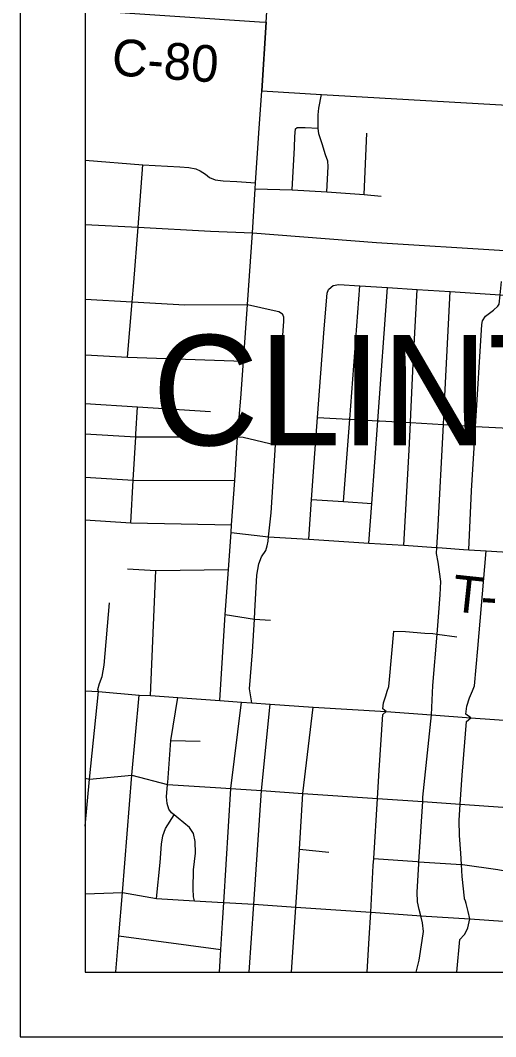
# Model space of a CAD drawing. Extents: x 0 to 34, y 0 to 22.
# Drawn here: x 2 to 2.735, y 14 to 15.572 of the extents above; entities that cross this region are included whole.
import ezdxf

# ---------------------------------------------------------------- set-up
doc = ezdxf.new("R2010")
doc.units = 0
for name, color, linetype in [('GM_X_City_Street', 7, 'Continuous'), ('GM_X_Corporation', 7, 'Continuous'), ('GM_X_County_Road', 7, 'Continuous'), ('GM_X_County_Road_Text', 7, 'Continuous'), ('GM_X_Township_Road', 7, 'Continuous'), ('GM_X_Township_Road_Text', 7, 'Continuous'), ('GM_X_Township_Text', 7, 'Continuous'), ('SH_Data', 7, 'Continuous')]:
    doc.layers.add(name, color=color, linetype=linetype)

msp = doc.modelspace()

# ---------------------------------------------------------------- linework, layer by layer
at = {"layer": 'GM_X_City_Street'}
for p, q in [((2.3732, 15.4628), (2.3799, 15.5688)), ((2.3687, 15.397), (2.3732, 15.4628)), ((2.5314, 15.3024), (2.5358, 15.397)), ((2.3259, 14.7795), (2.3839, 14.7731)), ((2.6522, 14.756), (2.6849, 14.7535)), ((2.201, 14.5274), (2.2094, 14.7207)), ((2.2325, 14.4581), (2.2781, 14.457)), ((2.4314, 14.2897), (2.4771, 14.2852)), ((2.1522, 14.1557), (2.3101, 14.1349)), ((2.1476, 14.1004), (2.1507, 14.1))]:
    msp.add_line(p, q, dxfattribs=at)
for points in [[(2.3799, 15.5688), (2.3956, 15.8148), (2.4066, 15.9776), (2.4102, 16.0293), (2.415, 16.0976), (2.4151, 16.0995)], [(2.4739, 15.3063), (2.4758, 15.3458), (2.4753, 15.3537), (2.4719, 15.3639), (2.4665, 15.3805), (2.4617, 15.3963), (2.4606, 15.4048), (2.4606, 15.4254), (2.4617, 15.4359), (2.4656, 15.4571)], [(2.4202, 15.3094), (2.4236, 15.3749), (2.4245, 15.3921), (2.4256, 15.404), (2.4281, 15.4057), (2.4403, 15.4057), (2.4606, 15.4048)], [(2.3085, 14.5201), (2.3168, 14.6529), (2.3216, 14.7222), (2.3259, 14.7795), (2.3267, 14.7914), (2.3315, 14.8601), (2.3359, 14.9277), (2.3407, 14.9875), (2.3451, 15.0447), (2.351, 15.132), (2.3589, 15.2428), (2.3628, 15.3111), (2.3633, 15.3203), (2.3687, 15.397)], [(2.1, 15.3553), (2.1896, 15.3483), (2.2464, 15.3453), (2.2606, 15.3439), (2.2711, 15.3418), (2.2781, 15.339), (2.2862, 15.3336), (2.2927, 15.3285), (2.3011, 15.325), (2.3137, 15.3234), (2.3347, 15.3222), (2.3633, 15.3203)], [(2.1659, 15.0507), (2.1729, 15.1364), (2.1753, 15.1662), (2.182, 15.2516), (2.1896, 15.3483)], [(2.3628, 15.3111), (2.4202, 15.3094), (2.4739, 15.3063), (2.5314, 15.3024), (2.5579, 15.2998)], [(2.1, 15.2561), (2.182, 15.2516), (2.2942, 15.2455), (2.3589, 15.2428), (2.5506, 15.228)], [(2.6932, 14.753), (2.6975, 14.844), (2.7036, 14.9438), (2.7132, 15.1014), (2.7144, 15.107), (2.7189, 15.1143), (2.7315, 15.1237), (2.7383, 15.1294), (2.7404, 15.1326), (2.7419, 15.1474), (2.744, 15.1677)], [(2.4458, 14.7692), (2.4502, 14.8309), (2.4543, 14.8881), (2.4595, 14.9576), (2.4696, 15.0946), (2.4742, 15.1497), (2.4763, 15.1556), (2.4807, 15.1592)], [(2.4807, 15.1592), (2.4837, 15.1618), (2.4924, 15.1633), (2.5248, 15.1613), (2.5675, 15.1586), (2.6134, 15.1556), (2.6646, 15.1524), (2.7419, 15.1474), (2.8183, 15.1426), (2.8695, 15.1393), (2.9219, 15.136), (2.9607, 15.1335)], [(2.4998, 14.8275), (2.5093, 14.9548), (2.5248, 15.1613)], [(2.5388, 14.7633), (2.5433, 14.8246), (2.5526, 14.9524), (2.5675, 15.1586)], [(2.5931, 14.7599), (2.6012, 14.907), (2.603, 14.9495), (2.6035, 14.9624), (2.6073, 15.0403), (2.6134, 15.1556)], [(2.612, 14.1), (2.6167, 14.1185), (2.6212, 14.1489), (2.6235, 14.1625), (2.6216, 14.1762), (2.619, 14.1871), (2.6167, 14.1967), (2.6141, 14.2085), (2.6133, 14.2237), (2.616, 14.2673), (2.6162, 14.2705), (2.6221, 14.3636), (2.6225, 14.3702), (2.6358, 14.4976), (2.6378, 14.5429), (2.6442, 14.6223), (2.6469, 14.6561), (2.6492, 14.6834), (2.65, 14.7039), (2.6462, 14.7339), (2.6436, 14.7472), (2.6441, 14.7566), (2.6455, 14.7806), (2.6541, 14.9466), (2.6559, 14.9806), (2.6646, 15.1524)], [(2.1, 15.1407), (2.1729, 15.1364), (2.2543, 15.1317), (2.351, 15.132), (2.3922, 15.1231), (2.3998, 15.1212), (2.4051, 15.1177)], [(2.358, 14.5164), (2.3545, 14.5381), (2.3589, 14.595), (2.3618, 14.6458), (2.3625, 14.6576), (2.3657, 14.7137), (2.3685, 14.7312), (2.3728, 14.7421), (2.3793, 14.752), (2.3816, 14.7588), (2.3832, 14.7663), (2.3839, 14.7731), (2.3878, 14.8103), (2.3947, 14.9153), (2.4024, 15.0346), (2.4073, 15.1059), (2.4073, 15.1127), (2.4051, 15.1177)], [(2.1, 15.0543), (2.1098, 15.0537), (2.1659, 15.0507), (2.3451, 15.0447)], [(2.1, 14.9793), (2.1811, 14.974), (2.2941, 14.9665)], [(2.1707, 14.7948), (2.1745, 14.8605), (2.1784, 14.9278), (2.1786, 14.9318), (2.1811, 14.974)], [(2.4595, 14.9576), (2.5072, 14.9549), (2.5093, 14.9548), (2.5526, 14.9524), (2.555, 14.9522), (2.603, 14.9495), (2.6541, 14.9466), (2.7036, 14.9438), (2.7553, 14.9409), (2.8065, 14.938), (2.8564, 14.9351), (2.9087, 14.9322), (2.9465, 14.93)], [(2.1, 14.9323), (2.1784, 14.9278), (2.3359, 14.9277), (2.3446, 14.927), (2.3947, 14.9153)], [(2.1, 14.8654), (2.1745, 14.8605), (2.3315, 14.8601)], [(2.4502, 14.8309), (2.4998, 14.8275), (2.5433, 14.8246)], [(2.1, 14.7992), (2.1707, 14.7948), (2.3267, 14.7914)], [(2.3839, 14.7731), (2.436, 14.7698), (2.4458, 14.7692), (2.5388, 14.7633), (2.5931, 14.7599), (2.6429, 14.7567), (2.6441, 14.7566), (2.6449, 14.7566), (2.6522, 14.756)], [(2.1659, 14.7237), (2.2094, 14.7207), (2.3216, 14.7222)], [(2.1, 14.3254), (2.1067, 14.398), (2.1207, 14.5336), (2.1199, 14.537), (2.1222, 14.546), (2.1264, 14.5572), (2.1294, 14.5746), (2.1377, 14.6707)], [(2.3168, 14.6529), (2.3618, 14.6458), (2.3869, 14.6441)], [(2.5361, 14.1), (2.5394, 14.1524), (2.5416, 14.1925), (2.5457, 14.2646), (2.5464, 14.2757), (2.5522, 14.3683), (2.5547, 14.4121), (2.5604, 14.4982), (2.5654, 14.5026), (2.5602, 14.5069), (2.5616, 14.516), (2.5649, 14.5269), (2.5673, 14.5345), (2.5697, 14.5416), (2.5707, 14.5522), (2.5774, 14.6272)], [(2.5774, 14.6272), (2.5952, 14.6268), (2.6255, 14.6239), (2.6376, 14.6232), (2.6442, 14.6223), (2.675, 14.6182)], [(2.1476, 14.1), (2.1476, 14.1004), (2.1522, 14.1557), (2.158, 14.2231), (2.1726, 14.4043), (2.1835, 14.5283)], [(2.2692, 14.2102), (2.2679, 14.2163), (2.2673, 14.2288), (2.2677, 14.258), (2.2706, 14.2837), (2.2705, 14.3016), (2.2676, 14.3142), (2.2615, 14.3236), (2.2439, 14.338), (2.2378, 14.3431), (2.2339, 14.3463), (2.2296, 14.3518), (2.2269, 14.3607), (2.2258, 14.371), (2.2275, 14.3899), (2.2278, 14.3933), (2.2325, 14.4581), (2.2437, 14.5243)], [(2.688, 14.2096), (2.6869, 14.213), (2.6868, 14.2141), (2.6831, 14.2477), (2.6821, 14.2665), (2.6812, 14.2839), (2.679, 14.3109), (2.6786, 14.3341), (2.6798, 14.3596), (2.6831, 14.4042), (2.6895, 14.4875), (2.6964, 14.4932), (2.6888, 14.4989), (2.6903, 14.511), (2.6945, 14.5238), (2.699, 14.5348)], [(2.308, 14.1), (2.3101, 14.1349), (2.3126, 14.1761), (2.3146, 14.2076), (2.3256, 14.3837), (2.3421, 14.5175)], [(2.354, 14.1), (2.3609, 14.2049), (2.3726, 14.3805), (2.3862, 14.5143)], [(2.4192, 14.1), (2.4258, 14.2004), (2.4288, 14.2468), (2.4314, 14.2897), (2.4367, 14.3761), (2.4527, 14.5096)], [(2.1, 14.3995), (2.1067, 14.398), (2.1726, 14.4043), (2.2275, 14.3899), (2.3099, 14.3848), (2.3256, 14.3837), (2.3332, 14.3832), (2.3726, 14.3805), (2.4367, 14.3761), (2.5522, 14.3683), (2.6221, 14.3636), (2.6798, 14.3596), (2.746, 14.3551), (2.7731, 14.3533), (2.8134, 14.3507), (2.8682, 14.3471), (2.8706, 14.3469), (3.0509, 14.3442), (3.0885, 14.3328), (3.1192, 14.331), (3.2575, 14.3197), (3.2613, 14.3182), (3.2636, 14.3155)], [(2.2105, 14.2135), (2.2161, 14.2692), (2.2184, 14.2976), (2.2204, 14.3108), (2.2242, 14.3217), (2.2378, 14.3431)], [(2.5464, 14.2757), (2.6137, 14.2707), (2.6162, 14.2705), (2.6821, 14.2665), (2.6834, 14.2664), (2.7382, 14.2584), (2.7466, 14.2572), (2.7836, 14.252), (2.8086, 14.2484), (2.8092, 14.2484), (2.8184, 14.2479), (2.8203, 14.2477), (2.8294, 14.2479), (2.8409, 14.2514), (2.8517, 14.2588), (2.8587, 14.2674)], [(2.1, 14.2211), (2.158, 14.2231), (2.2105, 14.2135), (2.2692, 14.2102), (2.3135, 14.2077), (2.3146, 14.2076), (2.3515, 14.2055), (2.3609, 14.2049), (2.4258, 14.2004), (2.5416, 14.1925), (2.6129, 14.1876), (2.619, 14.1871), (2.6947, 14.182), (2.7465, 14.1785), (2.8006, 14.1749), (2.8024, 14.1748), (2.8986, 14.1683), (3.0397, 14.1672)], [(2.6824, 14.1536), (2.6832, 14.1545), (2.6871, 14.1587), (2.6916, 14.1684), (2.6947, 14.182), (2.6924, 14.1935), (2.689, 14.2061), (2.688, 14.2096)], [(2.6749, 14.1), (2.6792, 14.1502), (2.6824, 14.1536)]]:
    msp.add_lwpolyline(points, dxfattribs=at)
at = {"layer": 'GM_X_Corporation'}
msp.add_lwpolyline([(2.1, 20.9), (2.1, 14.1), (6.2395, 14.1)], dxfattribs=at)
at = {"layer": 'GM_X_County_Road'}
for p, q in [((2.1, 15.5875), (2.3699, 15.5694)), ((2.3699, 15.5694), (2.3799, 15.5688)), ((2.3799, 15.5688), (2.3732, 15.4628))]:
    msp.add_line(p, q, dxfattribs=at)
msp.add_lwpolyline([(2.1, 16.5143), (2.1, 14.1), (3.5033, 14.1), (3.5067, 14.1788), (3.5412, 14.6736), (3.5547, 14.8664), (3.6065, 15.7173), (3.6083, 15.7281), (3.6105, 15.7435), (3.6146, 15.8068), (3.6204, 15.8961), (3.634, 16.1053), (3.6418, 16.2257), (3.654, 16.4154), (3.6172, 16.4188), (3.4065, 16.4352), (3.1867, 16.4496), (3.1585, 16.4507), (3.0788, 16.4569), (2.884, 16.4676), (2.7034, 16.4752), (2.5328, 16.4826), (2.3641, 16.4932), (2.2435, 16.5033)], close=True, dxfattribs=at)
for points in [[(2.3732, 15.4628), (2.4656, 15.4571), (2.7977, 15.4379), (3.0635, 15.4196), (3.0705, 15.4192), (3.0764, 15.4188)], [(2.1, 14.535), (2.1207, 14.5336), (2.1835, 14.5283), (2.201, 14.5274), (2.2437, 14.5243), (2.3085, 14.5201), (2.3421, 14.5175), (2.358, 14.5164), (2.3862, 14.5143), (2.4527, 14.5096), (2.5654, 14.5026), (2.6358, 14.4976), (2.6964, 14.4932), (2.7626, 14.4885), (2.826, 14.4843), (2.8868, 14.4799), (3.06, 14.4692), (3.0696, 14.4686)]]:
    msp.add_lwpolyline(points, dxfattribs=at)
at = {"layer": 'GM_X_Township_Road'}
for points in [[(2.5506, 15.228), (2.7492, 15.2157), (3.0905, 15.1944), (3.2108, 15.187), (3.2421, 15.1873), (3.2514, 15.1856)], [(2.6849, 14.7535), (2.6932, 14.753), (2.7199, 14.7515), (2.7954, 14.7466), (2.8426, 14.7436), (2.9224, 14.7384), (3.0367, 14.731), (3.0887, 14.7325)], [(2.699, 14.5348), (2.7021, 14.5427), (2.7074, 14.6001), (2.7199, 14.7515)]]:
    msp.add_lwpolyline(points, dxfattribs=at)
at = {"layer": 'SH_Data'}
for p, q in [((2, 21), (2, 14)), ((2.1, 20.9), (2.1, 14.1)), ((2.1, 14.1), (8.9, 14.1)), ((2.1, 14.1), (2.1, 14.1)), ((2, 14), (9, 14))]:
    msp.add_line(p, q, dxfattribs=at)

# ---------------------------------------------------------------- texts
at = {"layer": 'GM_X_County_Road_Text'}
msp.add_text('C-80', height=0.05682, rotation=355.8896, dxfattribs=at).set_placement((2.1401, 15.487))
at = {"layer": 'GM_X_Township_Road_Text'}
for s, rotation, p in [('T', 353.9419, (2.6658, 14.6581)), ('-', 356.3005, (2.7106, 14.6534))]:
    msp.add_text(s, height=0.0568, rotation=rotation, dxfattribs=at).set_placement(p)
at = {"layer": 'GM_X_Township_Text'}
msp.add_text('CLINTON', height=0.17045, rotation=0, dxfattribs=at).set_placement((2.2039, 14.9145))

doc.saveas('drawing.dxf')
